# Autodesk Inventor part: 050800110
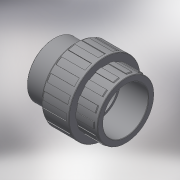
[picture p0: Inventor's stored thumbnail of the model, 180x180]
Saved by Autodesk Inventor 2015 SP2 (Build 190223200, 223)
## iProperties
Created: 2017-10
Part Number: 050800110
Material: Generic
Description: PLASSON UNION+O RING-CEM PVC 110
Document SubType Name: Modeling
Designer: Кирилл
Density: 1 g/cm^3
Appearance: Default
Author: Кирилл
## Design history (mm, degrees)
derived "050800.ipt"
feature "Solid1::050800.ipt"
tag "TaggingFeature1"
body "Solid1"
other parameters: "d0" = 145, "d5" = 132, "d6" = 137.5, "d7" = 140.8, "d8" = 151, "d9" = 61, "d10" = 61, "d11" = 99, "d12" = 104.5, "d14" = 45.75, "d15" = 45.75, "d16" = 20.7, "d17" = 6.1, "d19" = 147.98, "d20" = 6.1, "d21" = 4.53, "d25" = 15.1, "d26" = 7.55, "d27" = 42.66, "d28" = 0, "d32" = 15.1, "d33" = 7.55, "d35" = 0, "d39" = 1.1, "d45" = 1.65, "d49" = 360 deg, "d51" = 1.51, "d55" = 360 deg, "E_" = 151, "H_" = 145, "l_" = 61, "l_1" = 61, "Z_" = 23, "d13" = 23, "d24" = 47.4, "d40" = 1.65, "d44" = 1.51
